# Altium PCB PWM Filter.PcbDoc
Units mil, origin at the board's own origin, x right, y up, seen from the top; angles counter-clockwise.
Board outline 2700 x 2450 mil, 2 copper layers (Top Layer, Bottom Layer), stack 62 mil thick; 51 components, 17 nets, 102 pads, 0 vias.
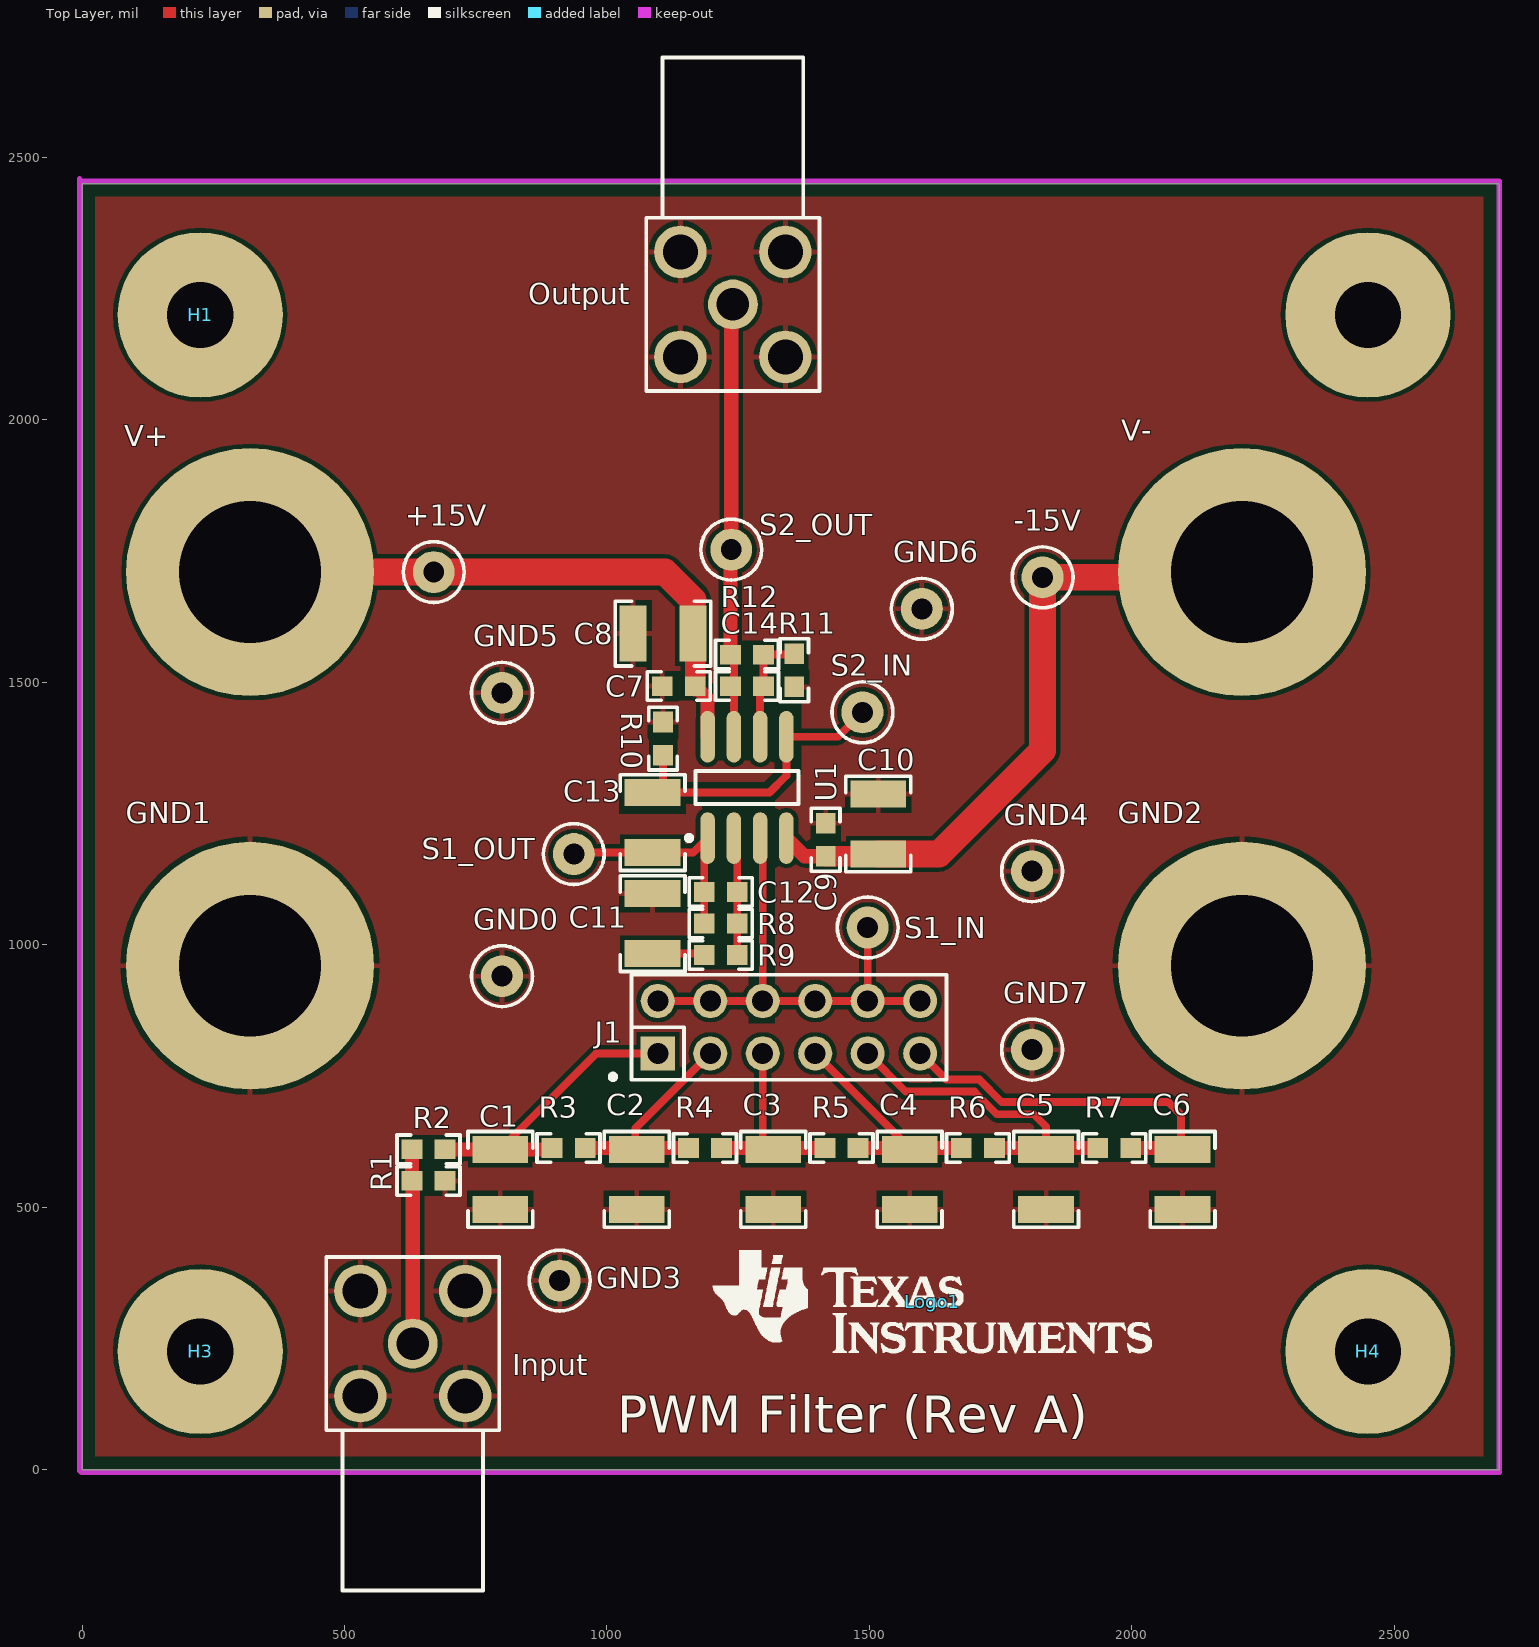
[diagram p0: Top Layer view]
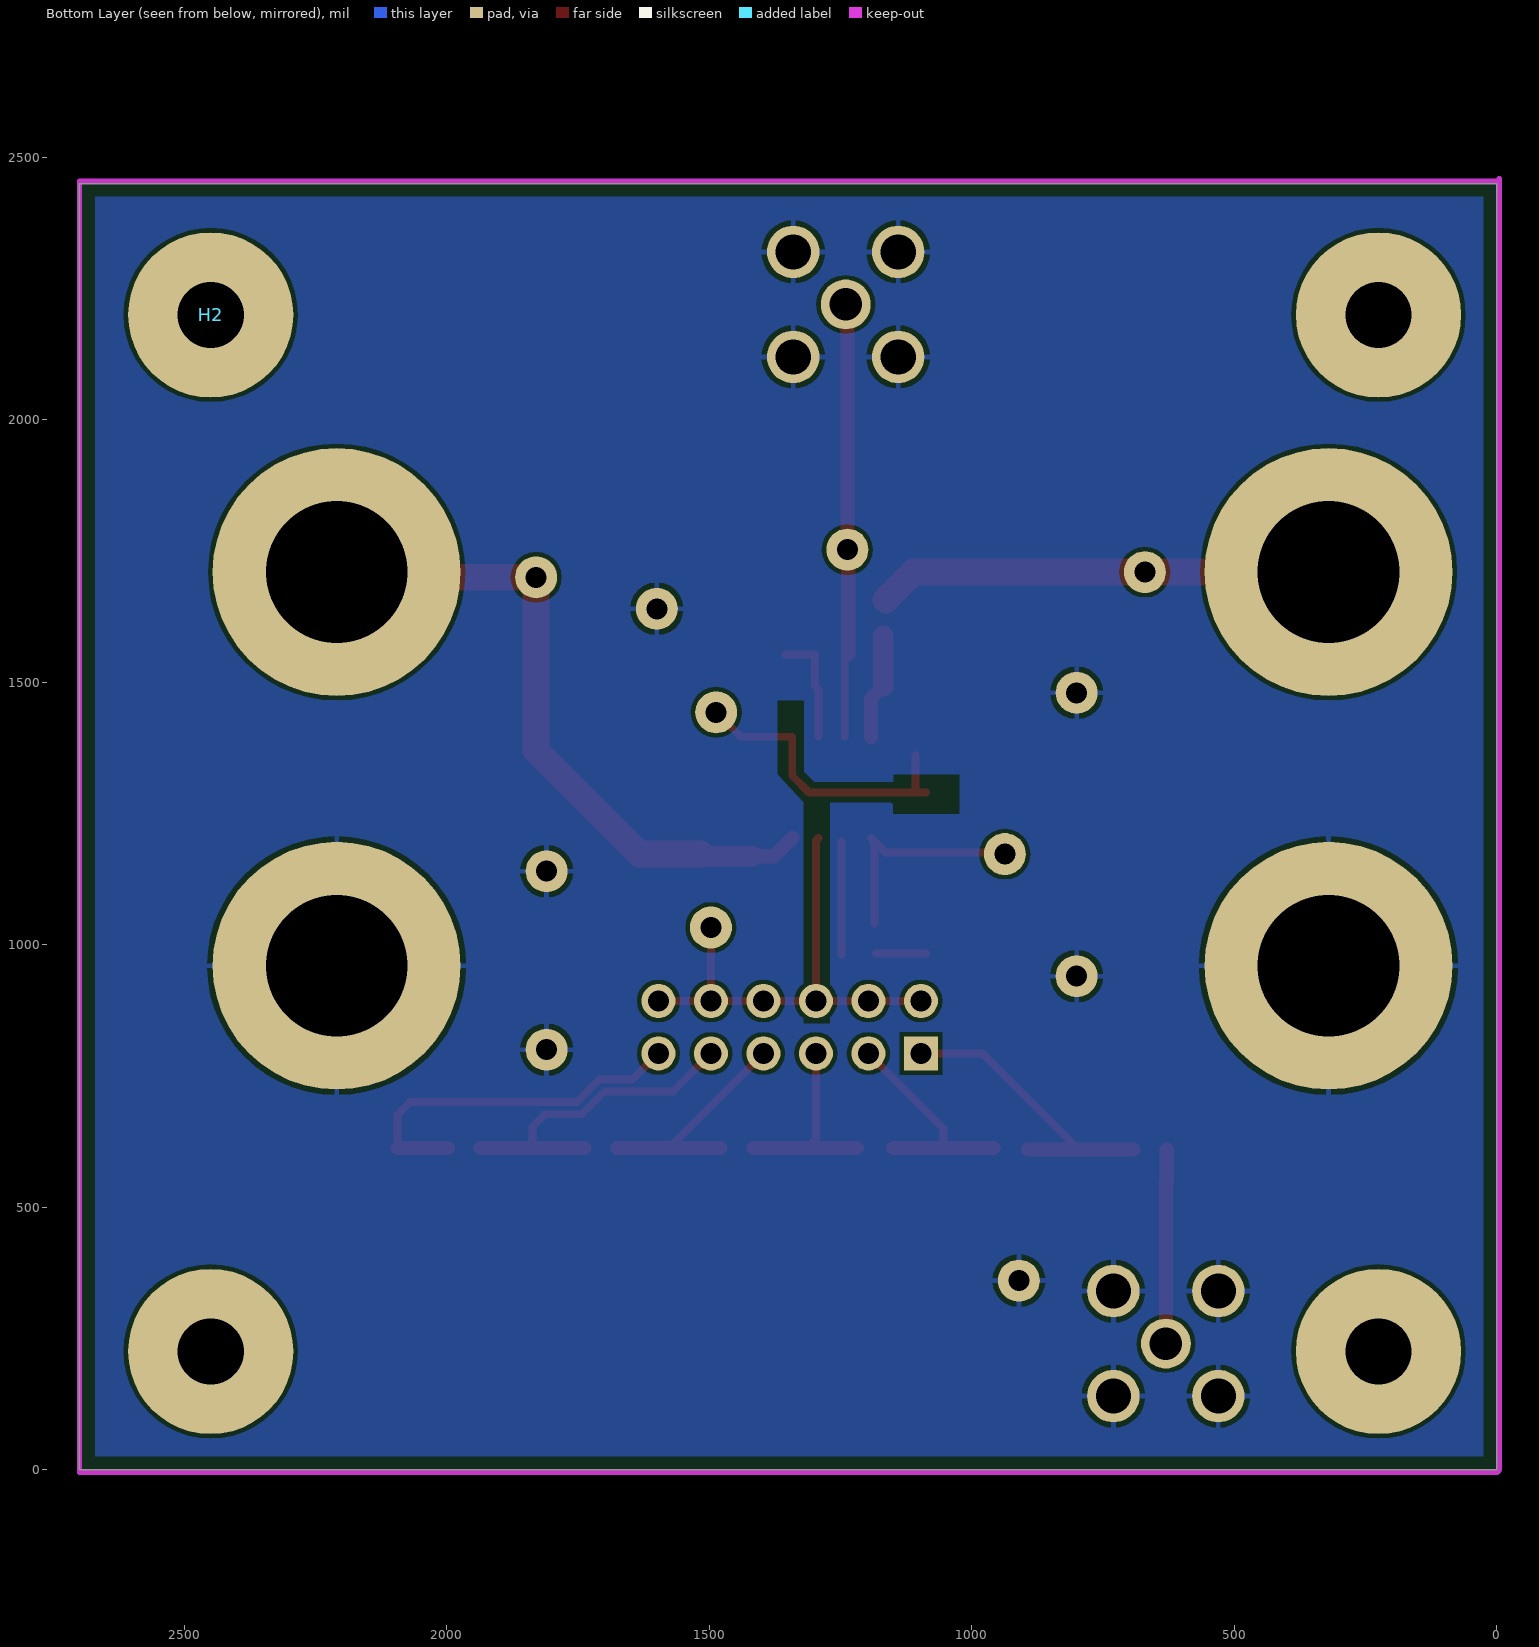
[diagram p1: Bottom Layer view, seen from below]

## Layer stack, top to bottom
Top Layer: signal copper 1.4
Dielectric: core 59.2, FR-4, Dk 4.8
Bottom Layer: signal copper 1.4

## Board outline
0,0 2700,0 2700,2450 0,2450 0,0

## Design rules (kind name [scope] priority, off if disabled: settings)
AcuteAngle [All] p1: minimum=4.50000000000000E+0001 checktracksonly=FALSE
AssemblyTestPointUsage [All] p1: valid=2
Clearance Clearance_BoardEdge_MountingHoles [OnCopper and InComponentClass('Mounting Holes') vs IsKeepOut] p1: gap=40
Clearance Clearance_BoardEdge_Poly [OnCopper and InPoly vs IsKeepOut] p2: gap=25
Clearance Clearance_BoardEdge [OnCopper and Not InComponentClass('Logo') and not InComponentClass('FiducialMark') and not InRegion(1000,500,4000,800) vs IsKeepOut] p3: gap=75
Clearance [All] p4: gap=8
ComponentClearance ComponentClearance_Logo [InComponentClass(Logo)] p1: gap=50 collisioncheckmode=3 verticalgap=10 showdistances=FALSE
ComponentClearance ComponentClearance_ScrewToNut [(HasFootprint('NY PMS 440 0025 PH')) vs (HasFootprint('Keystone_1902C'))] p2: gap=5 collisioncheckmode=3 verticalgap=10 showdistances=FALSE
ComponentClearance ComponentClearance_MountingHoles [InComponentClass('Mounting Holes')] p3: gap=10 collisioncheckmode=3 verticalgap=5 showdistances=FALSE
ComponentClearance ComponentClearance_SmallPassives [HasFootprint('0201*') or HasFootprint('0402*') or HasFootprint('0508') or HasFootprint('0603*') or HasFootprint('0612') or HasFootprint('0805*') or HasFootprint('0815*') or HasFootprint('0830*') or HasFootprint('1206*') or HasFootprint('1210*') or HasFootprint('1808*') or HasFootprint('1812*') or HasFootprint('1825*') or HasFootprint('2010*') or HasFootprint('2220*') or HasFootprint('2225*') or HasFootprint('2512*') or HasFootprint('2728*') or HasFootprint('3518*') vs HasFootprint('0201*') or HasFootprint('0402*') or HasFootprint('0508') or HasFootprint('0603*') or HasFootprint('0612') or HasFootprint('0805*') or HasFootprint('0815*') or HasFootprint('0830*') or HasFootprint('1206*') or HasFootprint('1210*') or HasFootprint('1808*') or HasFootprint('1812*') or HasFootprint('1825*') or HasFootprint('2010*') or HasFootprint('2220*') or HasFootprint('2225*') or HasFootprint('2512*') or HasFootprint('2728*') or HasFootprint('3518*')] p4: gap=20 collisioncheckmode=3 verticalgap=10 showdistances=FALSE
ComponentClearance ComponentClearance_THtoSMT [IsThruComponent vs IsSMTComponent] p5: gap=5 collisioncheckmode=3 verticalgap=5 showdistances=FALSE
ComponentClearance ComponentClearance_THtoTH [IsThruComponent vs IsThruComponent] p6: gap=5 collisioncheckmode=3 verticalgap=5 showdistances=FALSE
ComponentClearance [All] p7: gap=5 collisioncheckmode=3 verticalgap=10 showdistances=FALSE
DiffPairsRouting [All] p1: maxlimit=100 minlimit=10 mostfreqgap=10 maxuncoupledlength=1000
FabricationTestPointUsage TestPointUsage [All] p1: valid=2 allowmultiple=FALSE
FabricationTestpoint Testpoint [All] p1: side=3 testpointundercomponent=TRUE minsize=40 maxsize=100 preferedsize=60 minholesize=0 maxholesize=40 preferedholesize=32 testpointgrid=1 allowsidetop=TRUE allowsidebottom=TRUE usegrid=TRUE gridtolerance=0.01
FanoutControl Fanout_LCC [IsLCC] p1: bgadir=Out bgaviamode=Centered fanoutstyle=Auto fanoutdirection=Alternating viagrid=1 // Fanout_LCC (Default Rule)
FanoutControl Fanout_BGA [IsBGA] p2: bgadir=Out bgaviamode=Centered fanoutstyle=Auto fanoutdirection=Alternating viagrid=1 // Fanout_BGA (Default Rule)
FanoutControl Fanout_Default [All] p4: bgadir=Out bgaviamode=Centered fanoutstyle=Auto fanoutdirection=Alternating viagrid=1 // Fanout_Default (Default Rule)
FanoutControl Fanout_Small [(CompPinCount < 5)] p5: bgadir=Out bgaviamode=Centered fanoutstyle=Auto fanoutdirection=OutThenIn viagrid=1 // Fanout_Small (Default Rule)
HoleSize [All] p1: absolutevalues=TRUE maxlimit=251 minlimit=8 maxpercent=80.000 minpercent=20.000
MinimumAnnularRing [All] p1: minimumring=9
MinimumSolderMaskSliver MinimumSolderMaskSliver_Logo [InComponentClass('Logo') vs InComponentClass('Logo')] p1: minsoldermaskwidth=0.7
MinimumSolderMaskSliver [All] p2: minsoldermaskwidth=4
PlaneConnect [All] p1: planeconnectstyle=Relief reliefexpansion=10 reliefentries=4 reliefconductorwidth=10 reliefairgap=10
PolygonConnect [All] p1: connectstyle=Relief reliefconductorwidth=10 reliefentries=4 polygonreliefangle="90 Angle" airgapwidth=10
RoutingVias [All] p1: holewidth=16 width=34 viastyle="Through Hole" minholewidth=8 minwidth=26 maxholewidth=40 maxwidth=65
SMDToCorner [All] p1: distance=30000
SilkToSilkClearance [All] p1: silktosilkclearance=5
SilkscreenOverComponentPads [All] p1: minsilkscreentomaskgap=5
SolderMaskExpansion [All] p1: expansion=3
Width Width_1 [All] p1: maxlimit=60 minlimit=10 preferedwidth=27 bottomlayer_prefwidth=10 minimp=50.000000 maximp=50.000000 favimp=50.000000
Width [All] p2: maxlimit=100 minlimit=6 preferedwidth=10 checkconnectedcopper=TRUE
14 further rules are at their usual default settings.

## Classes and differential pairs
component class "Mounting Holes": H1 H2 H3 H4
component class Logo: Logo1
component class Hardware_ANSI-B: H1 H2 H3 H4 Logo1
component class Header: J1
component class "PWM Filter": +15V -15V C1 C2 C3 C4 C5 C6 C7 C8 C9 C10 C11 C12 C13 C14 GND0 GND1 GND2 GND3 GND4 GND6 GND7 Input J1 Output R1 R2 R3 R4 R5 R6 R7 R8 R9 R10 R11 R12 S1_IN S1_OUT S2_IN S2_OUT U1 V+ V-

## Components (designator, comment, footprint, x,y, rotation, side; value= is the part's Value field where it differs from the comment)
+15V "5000" Keystone5000 670,1710 r0 top
-15V "5000" Keystone5000 1830,1700 r0 top
C1 "4.7u" 1210 796.85,552.76 r270 top
C2 "470n" 1210 1056.85,552.76 r270 top
C3 "47n" 1210 1316.85,552.76 r270 top
C4 "4.7n" 1210 1576.85,552.76 r270 top
C5 "470p" 1210 1836.85,552.76 r270 top
C6 "47p" 1210 2096.85,552.76 r270 top
C7 "0.1u" 0603 1136.85,1492.76 r180 top
C8 "10u" 1210 1106.85,1592.76 r180 top
C9 "0.1u" 0603 1416.85,1200 r90 top
C10 "10u" 1210 1516.85,1230 r90 top
C11 "100u" 1210 1086.85,1040.32 r90 top
C12 "33p" 0603 1216.85,1100.32 r0 top
C13 "100u" 1210 1086.85,1232.76 r270 top
C14 "33p" 0603 1266.85,1492.76 r0 top
GND0 "5001" Keystone5001 800,940 r0 top
GND1 "108-0740-001" Johnson_108-0740-001 320,960 r0 top
GND2 "108-0740-001" Johnson_108-0740-001 2210,960 r0 top
GND3 "5001" Keystone5001 910,360 r0 top
GND4 "5001" Keystone5001 1810,1140 r0 top
GND5 "5001" Keystone5001 800,1480 r0 top
GND6 "5001" Keystone5001 1600,1640 r0 top
GND7 "5001" Keystone5001 1810,800 r0 top
H1 "NY PMS 440 0025 PH" "NY PMS 440 0025 PH" 225,2200 r0 top locked
H2 "NY PMS 440 0025 PH" "NY PMS 440 0025 PH" 2450,2200 r180 bottom locked
H3 "NY PMS 440 0025 PH" "NY PMS 440 0025 PH" 225,225 r0 top locked
H4 "NY PMS 440 0025 PH" "NY PMS 440 0025 PH" 2450,225 r0 top locked
Input "901-143" Amphenol_901-143 630,240 r90 top
J1 "TSW-106-07-G-D" TSW-106-07-G-D 1346.85,842.76 r0 top
Logo1 "Texas Instruments" TI_Stacked_Overlay_Small 1620,320 r0 top
Output "901-143" Amphenol_901-143 1240,2220 r270 top
R1 "50" 0603 660,550 r180 top
R2 "1.4k" 0603 660,610 r0 top
R3 "14k" 0603 926.85,612.76 r0 top
R4 "140k" 0603 1186.85,612.76 r0 top
R5 "1.4M" 0603 1446.85,612.76 r0 top
R6 "14M" 0603 1706.85,612.76 r0 top
R7 "140M" 0603 1966.85,612.76 r0 top
R8 "310k" 0603 1216.85,1040.32 r180 top
R9 "10k" 0603 1216.85,980.32 r0 top
R10 "10k" 0603 1106.85,1392.76 r270 top
R11 "10k" 0603 1356.85,1522.76 r90 top
R12 "310k" 0603 1266.85,1552.76 r180 top
S1_IN "5000" Keystone5000 1496.85,1032.76 r0 top
S1_OUT "5000" Keystone5000 936.85,1172.76 r90 top
S2_IN "5000" Keystone5000 1486.85,1442.76 r0 top
S2_OUT "5000" Keystone5000 1236.85,1752.76 r90 top
U1 "OPA2188" D0008A_M 1266.85,1299.68 r90 top
V+ "108-0740-001" Johnson_108-0740-001 320,1710 r0 top
V- "108-0740-001" Johnson_108-0740-001 2210,1710 r0 top

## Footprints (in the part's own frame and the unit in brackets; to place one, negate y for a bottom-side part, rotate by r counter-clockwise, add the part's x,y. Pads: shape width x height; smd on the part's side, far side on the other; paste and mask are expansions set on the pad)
0603 [mm] "0603 from SM-752 data"
  rect 1x0.95 smd: 1(-0.8,0) 2(0.8,0)
  silkscreen extent -1.52,-0.69 1.52,0.69, body extent -0.87,-0.47 0.87,0.47, height 0.85
1210 [mm] "1210 from SM-752 data"
  rect 1.3x2.7 smd: 1(-1.45,0) 2(1.45,0)
  silkscreen extent -2.32,-1.57 2.32,1.57, body extent -1.7,-1.35 1.7,1.35, height 1.35
Amphenol_901-143 [mil] "Amphenol recommended land pattern"
  round 95 hole 62: 1(0,0)
  round 100 hole 67: 2(100,100) 3(100,-100) 4(-100,-100) 5(-100,100)
  silkscreen extent -470,-165 165,165, body extent -456,-138 138,138, height 388
D0008A_M [mm] "SOIC, 8-Leads, Body 4.9x3.9mm, Pitch 1.27mm, IPC Low Density"
  oval 2.5x0.7 smd: 1(-2.45,1.905) 2(-2.45,0.635) 3(-2.45,-0.635) 4(-2.45,-1.905) 5(2.45,-1.905) 6(2.45,-0.635) 7(2.45,0.635) 8(2.45,1.905)
  silkscreen extent -2.57,-2.5 0.8,2.93, body extent -2,-2.5 2,2.5, height 1.75
Johnson_108-0740-001 [mm] "Banana Jack Uninsulated Standard Type"
  round 12 hole 6.858: 1(0,0)
  body extent -4.77,-5.43 4.75,5.57, height 2.39
Keystone5000 [mil] "For Keystone 500x miniature loop terminals"
  round 80 hole 40: 1(0,0)
  silkscreen extent -58,-58 58,58, body extent -49,-49 49,49, height 182
Keystone5001 [mil] "For Keystone 500x miniature loop terminals"
  round 80 hole 40: 1(0,0)
  silkscreen extent -58,-58 58,58, body extent -49,-49 49,49, height 182
"NY PMS 440 0025 PH" [mm] "4-40 nylon screw and mounting hole"
  round 8 hole 3.2: 1(0,0)
  body extent -3.3,-3.3 3.3,3.3, height 2.69
TI_Stacked_Overlay_Small [mil]
  silkscreen extent -418,-98 418,98
TSW-106-07-G-D [mm] "Samtec 100mil, 2x6, 230 mil above insulator"
  rect 1.65x1.65 hole 1.016 mask+0: 1(-6.35,-1.27)
  round 1.65 hole 1.016 mask+0: 2(-6.35,1.27) 3(-3.81,-1.27) 4(-3.81,1.27) 5(-1.27,-1.27) 6(-1.27,1.27) 7(1.27,-1.27) 8(1.27,1.27) 9(3.81,-1.27) 10(3.81,1.27) 11(6.35,-1.27) 12(6.35,1.27)
  silkscreen extent -8.64,-2.54 7.62,2.54, body extent -7.62,-2.54 7.62,2.54, height 8.38

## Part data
+15V -15V S1_IN S1_OUT S2_IN S2_OUT: "Test Point, TH, Miniature, Red"
C1 C2 C3 C4 C5 C6 C7 C8 C9 C10 C11 C12 C13 C14: library part Capacitor, "CAP, CERM, xxxF, xxV, [TempCo], xx%, [PackageReference]"
GND0 GND3 GND4 GND5 GND6 GND7: "Test Point, TH, Miniature, Black"
GND1 GND2 V+ V-: "Standard Banana Jack, Uninsulated, 15A"
H1 H2 H3 H4: "Machine Screw, Round, #4-40 x 1/4, Nylon, Philips panhead"
Input Output: "Connector, TH, Right Angle SMA 50 ohm"
J1: "Header, TH, 100mil, 6x2, Gold plated, 230 mil above insulator"
Logo1: library part TI_Logo, "Texas Instrument Corporate Signature"
R1 R2 R3 R4 R5 R6 R7 R8 R9 R10 R11 R12: library part Resistor, "RES, xxx ohm, x%, xW, [PackageReference]"

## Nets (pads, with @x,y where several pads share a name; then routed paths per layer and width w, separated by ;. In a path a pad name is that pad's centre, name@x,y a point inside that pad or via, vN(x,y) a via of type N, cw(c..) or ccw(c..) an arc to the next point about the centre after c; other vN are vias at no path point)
AVDD: +15V.1 C7.1 C8.1 U1.8 V+.1 | length 1067.9
  Top Layer w27: C7.1 1191.85,1469.25 U1.8
  Top Layer w39: C7.1 C8.1@1168.35,1588.35
  Top Layer w51: V+.1 +15V.1 1110.82,1710 1163.94,1656.89
AVSS: -15V.1 C9.1 C10.1 U1.4 V-.1 | length 1279.8
  Top Layer w27: U1.4 1376.57,1168.5 C9.1
  Top Layer w39: C9.1 C10.1@1512.44,1168.5
  Top Layer w51: C10.1 1632.91,1172.91 1830,1370 -15V.1 V-.1@2200,1700
GND: C1.2 C2.2 C3.2 C4.2 C5.2 C6.2 C7.2 C8.2 C9.2 C10.2 C11.2 GND0.1 GND1.1 GND2.1 GND3.1 GND4.1 GND5.1 GND6.1 GND7.1 Input.2 Input.3 Input.4 Input.5 Output.2 Output.3 Output.4 Output.5 R1.1 R10.1 R11.1
NetC1_1: C1.1 J1.1 R2.2 R3.1 | length 576.9
  Top Layer w10: C1.1@796.69,610 C1.1
  Top Layer w15: C1.1@796.69,610 979.45,792.76 J1.1
  Top Layer w27: R2.2 C1.1@796.69,610 ; C1.1 R3.1@892.44,609.84
NetC2_1: C2.1 J1.3 R3.2 R4.1 | length 433.3
  Top Layer w15: C2.1@1053.94,612.76 1053.94,649.84 J1.3 ; R4.1@1149.53,609.84 R4.1@1152.44,609.84
  Top Layer w27: R3.2 1053.94,612.76 R4.1@1149.53,612.76
NetC3_1: C3.1 J1.5 R4.2 R5.1 | length 384.1
  Top Layer w15: J1.5 1296.85,629.84 C3.1@1313.94,612.76
  Top Layer w27: R4.2 1313.94,612.76 R5.1
NetC4_1: C4.1 J1.7 R5.2 R6.1 | length 451.6
  Top Layer w15: J1.7 C4.1@1576.85,612.76
  Top Layer w27: R5.2 1576.85,612.76 R6.1
NetC5_1: C5.1 J1.9 R6.2 R7.1 | length 638.1
  Top Layer w15: J1.9 1569.61,720 1700,720 1743,677 1813,677 1836.85,653.15 1836.85,612.76 C5.1
  Top Layer w27: R6.2 1836.85,612.76 R7.1
NetC6_1: C6.1 J1.11 R7.2 | length 704.3
  Top Layer w15: J1.11 1646.61,743 1709.53,743 1752.53,700 2070,700 2093.94,676.06 C6.1@2093.94,612.76
  Top Layer w27: R7.2 C6.1@2093.94,612.76
NetC11_1: C11.1 R9.1 | length 95.6
  Top Layer w15: C11.1 R9.1@1182.44,983.23
NetC12_1: C12.1 C13.2 R8.2 S1_OUT.1 U1.1 | length 419.9
  Top Layer w15: S1_OUT.1@939.76,1175.67 C13.2 1164.29,1175.67 U1.1@1185.35,1196.73 ; R8.2 U1.1@1185.35,1196.73 ; U1.1 U1.1@1185.35,1196.73
NetC12_2: C12.2 R8.1 R9.2 U1.2 | length 216.4
  Top Layer w15: R9.2 C12.2 U1.2@1248.35,1196.73
NetC13_1: C13.1 R10.2 S2_IN.1 U1.5 | length 579.4
  Top Layer w15: C13.1 C13.1@1104.05,1289.84 ; R10.2 1106.85,1292.65 C13.1@1104.05,1289.84 ; S2_IN.1 1440.24,1396.14 U1.5 1341.85,1321.85 1309.84,1289.84 C13.1@1104.05,1289.84
NetC14_1: C14.1 Output.1 R12.2 S2_OUT.1 U1.7 | length 841.9
  Top Layer w15: R12.2 1241.85,1546.26 U1.7
  Top Layer w27: R12.2 S2_OUT.1@1235.35,1751.26 ; S2_OUT.1 Output.1@1236.85,2236.85
NetC14_2: C14.2 R11.2 R12.1 U1.6 | length 216.3
  Top Layer w15: U1.6 1291.85,1486.26 C14.2 R12.1 R11.2@1355.35,1552.76
NetInput_1: Input.1 R1.2 R2.1 | length 370.6
  Top Layer w27: R2.1 R1.2 630,548.5 Input.1
NetJ1_2: J1.2 J1.4 J1.6 J1.8 J1.10 J1.12 S1_IN.1 U1.3 | length 952.5
  Top Layer w15: J1.2 J1.4 J1.6 ; U1.3 1296.85,1198.23 J1.6 ; S1_IN.1 J1.10 ; J1.12 J1.10 ; J1.6 J1.8 J1.10
pads on no net: H1.1 H2.1 H3.1 H4.1

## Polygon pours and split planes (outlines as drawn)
GND on Bottom Layer "Bottom Layer-No Net" (solid, remove dead copper, pour order 4): 0,0 0,2455 2700,2455 2700,-5 0,-5 0,0
GND on Top Layer "Top Layer-No Net" (solid, remove dead copper, pour order 6): 0,0 0,2455 2700,2455 2700,-5 0,-5 0,0

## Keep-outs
Keep-Out Layer:
  lines w10: -5,2460 -5,0 ; 0,2455 2700,2455 2700,0 ; 2700,-5 0,-5 ; -5,0 ccw(c0,0) 0,-5 ; -5,0 ccw(c0,0) 0,-5 ; -5,0 ccw(c0,0) 0,-5 ; -5,0 ccw(c0,0) 0,-5 ; -5,0 ccw(c0,0) 0,-5 ; -5,0 ccw(c0,0) 0,-5

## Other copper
Top Layer:
  pour cut-out: 1025.13,1323.96 1148.57,1323.96 1148.57,1310 1300,1310 1320,1330 1320,1464.21 1320.83,1465.04 1370,1465.04 1370,1324.72 1320,1274.72 1320,1268.19 1150.55,1268.19 1149.84,1268.9 1149.84,1250 1023.86,1250 1023.86,1325.28
  pour cut-out: 1320,1268.19 1320,850 1270,850 1270,1268.19
Bottom Layer:
  pour cut-out: 1270,850 1270,1268.19 1320,1268.19 1320,850
  pour cut-out: 1025.13,1323.96 1148.57,1323.96 1148.74,1323.79 1148.74,1310 1300,1310 1320,1330 1320,1464.21 1320.83,1465.04 1370,1465.04 1370,1324.72 1320,1274.72 1320,1271.46 1153.82,1271.46 1150.55,1268.19 1149.84,1268.9 1149.84,1250 1023.86,1250 1023.86,1323.98 1024.49,1324.62

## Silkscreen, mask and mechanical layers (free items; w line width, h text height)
Top Overlay:
  text "PWM Filter (Rev A)" at 1020,70 h70
M1 Board Outline:
  lines w10: -10,2455 2700,2455 2700,-5 0,-5 0,2455
M2 Board Dimensions:
  rectangle: 3879.5,-85.5 4004.5,39.5
  rectangle: 4004.5,-210.5 4379.5,-85.5
  lines w7: 3879.5,-85.5 4879.5,-85.5 ; 4004.5,-210.5 4004.5,39.5 ; 4129.5,-210.5 4129.5,39.5 ; 4379.5,-210.5 4379.5,39.5 ; 4629.5,-210.5 4629.5,39.5 ; 3879.5,-210.5 4879.5,-210.5 4879.5,39.5 3879.5,39.5 3879.5,-210.5
  lines w10: 3879.5,-275.5 3879.5,-255.5 ; 3939.5,-285.5 3879.5,-265.5 ; 3939.5,-245.5 3879.5,-265.5 ; 4103.58,-265.5 3879.5,-265.5 ; 4655.42,-265.5 4879.5,-265.5 ; 4819.5,-285.5 4879.5,-265.5 ; 4819.5,-245.5 4879.5,-265.5 ; 4879.5,-275.5 4879.5,-255.5
  text "1000 (mil)" at 4113.58,-301.49 h60
M5 Assembly Top:
  lines w10: -292,-930.17 6308,-930.17 ; -292,-726.83 6310,-726.83 ; -292,-523.5 -292,-1133.5 3713,-1133.5 6310,-1133.5 6310,-523.5 -291.5,-523.5 -291.5,-1133.5 1284,-1133.5 ; 2173,-1133.5 2173,-523.5 ; 3440,-726.83 3440,-523.5 ; 4280,-726.83 4280,-523.5 ; 4902,-1140 4902,-937.17
M6 Assembly Bottom:
  lines w10: -292.5,-727.33 6309.5,-727.33 ; -290.5,-930.67 6309.5,-930.67 ; 1115.5,-1140.5 1115.5,-937.67 ; 1737.5,-727.33 1737.5,-524 ; 2577.5,-727.33 2577.5,-524 ; 3844.5,-1134 3844.5,-524 ; 4733.5,-1134 6309,-1134 6309,-524 -292.5,-524 -292.5,-1134 2304.5,-1134 6309.5,-1134 6309.5,-524
M9 Title Sheet:
  drawing of 57 lines, arcs and shapes, not listed
  text "1" at 739.84,8036.5 h70
  text "2" at 3235.5,8036.5 h70
  text "3" at 5724.84,8036.5 h70
  text "4" at 8231.51,8036.5 h70
  text "5" at 10730.5,8036.5 h70
  text "6" at 13235.5,8036.5 h70
  text "A" at -416.5,6893.5 h70
  text "A" at 14383.5,6893.5 h70
  text "B" at -416.5,4513.5 h70
  text "B" at 14383.5,4513.5 h70
  text "C" at -416.5,2138.5 h70
  text "C" at 14383.5,2138.5 h70
  text "PROJECT TITLE:" at 11343.5,277.5 h45
  text ".PRJ_Title" at 11393.5,144.17 h70
  text "DESIGNED FOR:" at 11343.5,-23.5 h45
  text ".PRJ_Customer" at 11393.5,-163.5 h70
  text "D" at -416.5,-231.5 h70
  text "D" at 14383.5,-231.5 h70
  text "FILE NAME:" at 11343.5,-323.5 h45
  text ".PCB_File_Name_No_Path" at 11393.5,-443.5 h70
  text "Texas Instruments (TI) and/or its licensors do not warrant the accuracy or completeness of this specification" at 6374,-605.34 h45
  text "ENGINEER:" at 11343.5,-613.5 h45
  text "LAYOUT BY:" at 12848.5,-613.5 h45
  text "or any information contained therein. TI and/or its licensors do not warrant that this design will meet" at 6329.01,-718 h45
  text ".PRJ_Engineer" at 11393.5,-768.49 h70
  text ".PCB_Layout" at 12899,-768.49 h70
  text "the specifications, will be suitable for your application or fit for any particular purpose, or will operate in" at 6329.01,-830.67 h45
  text ".Layer_Name" at 577,-858.49 h60
  text "ALTIUM DESIGNER VERSION:" at 12848.5,-923.5 h45
  text "an implementation. TI and/or its licensors do not warrant that the design is production worthy. You should" at 6329.01,-943.33 h45
  text "completely validate and test your design implementation to confirm the system functionality for your application." at 6374,-1056 h45
  text ".print_Scale" at 11393.5,-1056.83 h70
  text ".Application_BuildNumber" at 12899,-1056.83 h70
  text "1" at 739.84,-1263.5 h70
  text "2" at 3235.5,-1263.5 h70
  text "3" at 5724.84,-1263.5 h70
  text "4" at 8231.51,-1263.5 h70
  text "5" at 10730.5,-1263.5 h70
  text "6" at 13235.5,-1263.5 h70
M10 Fab Notes:
  drawing of 203 lines, arcs and shapes, not listed
  text "DESIGN INFORMATION" at 12381.02,6810 h60
  text "(REFER ALSO ARRAY/PANEL PROFILING INFORMATION)" at 12019.46,6648.29 h60
  text "BOARD SIZE" at 11333.46,6644 h60
  text "3450MIL" at 11795.78,6516.18 h60
  text "X" at 12301.46,6516.18 h60
  text "4950MIL" at 12532.78,6516.18 h60
  text "Number of Layers :" at 11736.46,6319 h60
  text "2" at 12831.27,6309 h60
  text "MIN. TRACK WIDTH:" at 11736.46,6180 h60
  text "8" at 12832.7,6180 h60
  text "MIL" at 12987.46,6180 h60
  text "MIN. CLEARANCE:" at 11736.46,6048 h60
  text "8" at 12832.7,6048 h60
  text "MIL" at 12987.46,6048 h60
  text "MIN. VIA PAD SIZE:" at 11736.46,5916 h60
  text "24" at 12802.71,5916 h60
  text "MIL" at 12987.46,5916 h60
  text "0.05mm (2MIL)" at 12431.46,5774.29 h60
  text "MINIMUM ANNULAR RING" at 11407.23,5770 h60
  text "EXTERNAL" at 13139.46,5770 h60
  text "PER" at 11607.23,5652 h60
  text "IPC-D-275 CLASS 2 LEVEL C" at 11827.23,5652 h60
  text "MIL, HOLES" at 13315.46,5539.71 h60
  text "+/-" at 12923,5539 h60
  text "+/-" at 13777,5539 h60
  text "REGISTRATION TOLERANCES:" at 11407.23,5534 h60
  text "METAL" at 12607,5534 h60
  text "5" at 13183.2,5534 h60
  text "3" at 14016.2,5534 h60
  text "MIL" at 14132.46,5534 h60
  text "MATERIAL:" at 11332.46,5324.54 h60
  text "FR-4 High Tg" at 12318.9,5184.21 h60
  text "FR-4" at 11793.46,5175.64 h60
  text "X" at 12165.46,5175.64 h60
  text "OTHER" at 13241.46,5175.64 h60
  text "62 MIL (1.6mm) +/-10%" at 12073.56,5012.92 h60
  text "THICKNESS:" at 11407.23,5008.64 h60
  text "X" at 11945.4,5008.64 h60
  text "OTHER" at 13358.46,5008.64 h60
  text "TOLERANCE:" at 11407.23,4850.64 h60
  text "X" at 12246.53,4850.64 h60
  text "ANSI IPC-6012 TYPE 3 CLASS 2" at 12433.48,4850.64 h60
  text "OTHER +/-" at 12433.46,4694.64 h60
  text "BOW & TWIST:" at 11407.23,4537.64 h60
  text "X" at 12246.53,4537.64 h60
  text "ANSI IPC-6012 TYPE 3 CLASS 2" at 12433.48,4537.64 h60
  text "OTHER +/-" at 12433.46,4379.13 h60
  text "COPPER THICKNESS (FINISHED):" at 11332.46,4243.64 h60
  text "1.4MIL (1oz)" at 12212.46,4090.92 h60
  text "2MIL (1.4oz)" at 12979.46,4090.92 h60
  text "2.8MIL (2oz)" at 13706.46,4090.92 h60
  text "OUTER:" at 11689.46,4086.64 h60
  text "X" at 12084,4086 h60
  text "1.4MIL (1oz)" at 12562.46,3933.92 h60
  text "2.8MIL (2oz)" at 13406.46,3933.92 h60
  text "INNER SIGNAL:" at 11689.46,3929.64 h60
  text "X" at 12435.42,3929.64 h60
  text "DRILLING:" at 11332.46,3790.64 h60
  text "REFERENCE:" at 11407.23,3673.64 h60
  text "X" at 12055.46,3673.64 h60
  text "AS SHOWN" at 12242.46,3673.64 h60
  text "X" at 12956.46,3673.64 h60
  text "NC_DRILL FILES" at 13093.46,3673.64 h60
  text "PTH MIN COPPER THICKNESS:" at 11407.23,3515.64 h60
  text "X" at 12757.46,3515.64 h60
  text "1MIL" at 12894.46,3515.64 h60
  text "OTHER" at 13391.46,3515.64 h60
  text "BOARD FINISH:" at 11332.46,3356.64 h60
  text "SILKSCREEN:" at 11487.68,3238.64 h60
  text "X" at 12436.46,3238.64 h60
  text "TOP" at 12562.46,3238.64 h60
  text "X" at 12946.46,3238.64 h60
  text "BOTTOM" at 13073.46,3238.64 h60
  text "SILKSCREEN COLOR:" at 11487.68,3071.64 h60
  text "X" at 12435.42,3071.64 h60
  text "WHITE" at 12562.46,3071.64 h60
  text "OTHER" at 13073.46,3071.64 h60
  text "SOLDER RESIST COLOR:" at 11487.68,2901.64 h60
  text "X" at 12055.42,2742.44 h60
  text "GREEN" at 12182.46,2742.44 h60
  text "BLUE" at 12773.46,2742.44 h60
  text "OTHER" at 13311.46,2742.44 h60
  text "IMMERSION GOLD (ENIG)" at 12393.46,2553.92 h60
  text "SURFACE FINISH:" at 11332.46,2549.64 h60
  text "X" at 12206.51,2549.64 h60
  text "Pb-FREE HASL" at 13625.75,2549.64 h60
  text "OTHER" at 12393.46,2392.64 h60
  text "ARRAY/PANEL:" at 11332.46,2213.64 h60
  text "CUT AND TRIM PER MECH LAYER 1" at 12393.46,2209.35 h60
  text "N.C. ROUTE" at 12393.46,2057.64 h60
  text "X" at 13072.46,2057.64 h60
  text "V. SCORE" at 13259.46,2057.64 h60
  text "CERTIFICATION:" at 11332.46,1920.64 h60
  text "MATERIALS AND WORKMANSHIP FOR ALL PCBS" at 12057.46,1920.64 h60
  text "TO MEET OR EXCEED THE REQUIREMENTS OF:" at 12057.46,1822.64 h60
  text "X" at 11683.96,1686.13 h60
  text "ANSI IPC-A-600F CLASS ->" at 11822.96,1686.13 h60
  text "X" at 13462.02,1686.13 h60
  text "2" at 13580.96,1686.14 h60
  text "1" at 13265.96,1684.64 h60
  text "3" at 13934.96,1684.64 h60
  text "X" at 11686.02,1526.64 h60
  text "UL 94V-0" at 11822.96,1526.64 h60
  text "X" at 12498.02,1526.64 h60
  text "RoHS" at 12634.96,1526.64 h60
  text "OTHER" at 13279.36,1526.64 h60
  text "PER ORDER" at 13676.42,1526.64 h60
  text "ADDITIONAL REQUIREMENTS:" at 11332.46,1385.64 h60
  text "MICROSECTION:" at 11407.23,1270.64 h60
  text "YES" at 12312.96,1270.64 h60
  text "REQUIRED" at 13174.46,1114.49 h60
  text "BARE BOARD ELEC. TEST:" at 11407.23,1111.64 h60
  text "NONE" at 12712.96,1111.64 h60
  text "X" at 13047.46,1111.64 h60
  text "PER ORDER" at 13766.46,1111.64 h60
  text "MANUFACTURER'S ID/LOGO:" at 11407.23,954.64 h60
  text "RAIL" at 12872.96,950.35 h60
  text "X" at 13247.46,950.35 h60
  text "METAL" at 13364.77,950.35 h60
  text "SILK" at 13876.46,950.35 h60
M11 Gerber Information:
  lines w10: -292,-930.17 6308,-930.17 ; -292,-726.83 6310,-726.83 ; -292,-523.5 -292,-1133.5 3713,-1133.5 6310,-1133.5 6310,-523.5 -291.5,-523.5 -291.5,-1133.5 1284,-1133.5 ; 2173,-1133.5 2173,-523.5 ; 3440,-726.83 3440,-523.5 ; 4280,-726.83 4280,-523.5 ; 4902,-1140 4902,-937.17
M12 Stackup:
  lines w6: 11360,7460 13910,7460 ; 11360,7564.4 13910,7564.4 ; 11300,6975 ccw(c11334,6975) 11334,6941 13936,6941 ccw(c13936,6975) 13970,6975 13970,7681 ccw(c13936,7681) 13936,7715 11334,7715 ccw(c11334,7681) 11300,7681 11300,6975
  text "The Stackup Legend below this is static." at 11605.5,7874.5 h60
  text "If you change the stackup, update the Legend." at 11615.5,7784.5 h60
  text "Layer Stack Up Detail for: Ref_Design.PcbDoc" at 11360,7597.1 h57
  text "Layer" at 11360,7525.4 h24
  text "Gerber" at 12255.81,7525.4 h24
  text "Copper" at 12819.33,7525.4 h24
  text "Dielectric" at 13422.04,7525.4 h24
  text "Name" at 11360,7477.4 h24
  text "Document" at 12255.81,7477.4 h24
  text "Thickness" at 12819.33,7477.4 h24
  text "Material" at 13422.04,7477.4 h24
  text "Top Solder Mask" at 11360,7384.44 h34
  text "(.GTS)" at 12255.81,7384.44 h34
  text "Solder Resist" at 13422.04,7384.44 h34
  text "Top Layer" at 11360,7287.69 h34
  text "(.GTL)" at 12255.81,7287.69 h34
  text "1.4mil" at 12819.33,7287.69 h34
  text "FR-4" at 13422.04,7239.31 h34
  text "Bottom Layer" at 11360,7190.94 h34
  text "(.GBL)" at 12255.81,7190.94 h34
  text "1.4mil" at 12819.33,7190.94 h34
  text "Bottom Solder Mask" at 11360,7094.19 h34
  text "(.GBS)" at 12255.81,7094.19 h34
  text "Solder Resist" at 13422.04,7094.19 h34

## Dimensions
0,0 to 0,2450 on M2 Board Dimensions
0,0 to 2700,0 on M2 Board Dimensions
